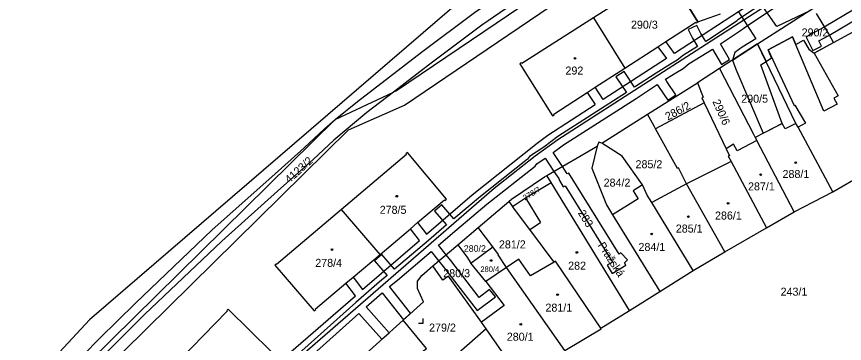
# Model space of a CAD drawing. Extents: x -869103 to -863415, y -1015889 to -1012477.
# Drawn here: x -867399.9 to -867224, y -1013871.7 to -1013802.3 of the extents above; entities that cross this region are included whole.
import ezdxf

# ---------------------------------------------------------------- set-up
doc = ezdxf.new("R2010")
doc.units = 0
for name, color, linetype in [('Hranice parcel', 7, 'Continuous'), ('Parcelní čísla', 7, 'Continuous'), ('Pop  PČ popisy', 7, 'Continuous'), ('Vnitřní kresba', 7, 'Continuous'), ('Věcná břemena k části', 7, 'Continuous'), ('Značky budov', 7, 'Continuous'), ('Značky kultur', 7, 'Continuous')]:
    doc.layers.add(name, color=color, linetype=linetype)

msp = doc.modelspace()

# ---------------------------------------------------------------- linework, layer by layer
at = {"layer": 'Hranice parcel'}
for p, q in [((-867277.34, -1013802.56), (-867270.69, -1013813.22)), ((-867242.47, -1013808.08), (-867250.56, -1013813.33)), ((-867234.33, -1013824.97), (-867242.47, -1013808.08)), ((-867250.56, -1013813.33), (-867255.27, -1013816.38)), ((-867265.84, -1013823.02), (-867255.27, -1013816.38)), ((-867332.19, -1013824.13), (-867319.83, -1013818.34)), ((-867253.84, -1013820.61), (-867264.15, -1013826.09)), ((-867253.84, -1013820.61), (-867249.16, -1013830.36)), ((-867275.59, -1013829.14), (-867265.84, -1013823.02)), ((-867264.43, -1013825.58), (-867265.84, -1013823.02)), ((-867264.15, -1013826.09), (-867264.43, -1013825.58)), ((-867233.85, -1013825.73), (-867234.33, -1013824.97)), ((-867226.53, -1013839.51), (-867233.85, -1013825.73)), ((-867243, -1013827.93), (-867242.65, -1013828.58)), ((-867287.23, -1013836.04), (-867276.54, -1013829.8)), ((-867234.74, -1013843.75), (-867242.65, -1013828.58)), ((-867226.53, -1013839.51), (-867209.64, -1013829.72)), ((-867286.34, -1013837.49), (-867287.23, -1013836.04)), ((-867269.71, -1013864.68), (-867286.34, -1013837.49)), ((-867257.58, -1013837.77), (-867264.97, -1013841.75)), ((-867249.43, -1013852.24), (-867257.58, -1013837.77)), ((-867234.74, -1013843.75), (-867226.53, -1013839.51)), ((-867301.8, -1013847.07), (-867295.3, -1013841.57)), ((-867295.3, -1013841.57), (-867294.72, -1013841.08)), ((-867295.3, -1013841.57), (-867294.53, -1013842.6)), ((-867256.18, -1013856.17), (-867264.97, -1013841.75)), ((-867322.67, -1013852.76), (-867330.82, -1013843.22)), ((-867240.56, -1013847.11), (-867234.74, -1013843.75)), ((-867273.26, -1013844.36), (-867263.25, -1013860.65)), ((-867306.15, -1013850.76), (-867301.8, -1013847.07)), ((-867298.73, -1013851.16), (-867301.8, -1013847.07)), ((-867249.43, -1013852.24), (-867240.56, -1013847.11)), ((-867311.44, -1013855.23), (-867306.15, -1013850.76)), ((-867306.15, -1013850.76), (-867304.22, -1013853.28)), ((-867303.38, -1013854.64), (-867298.73, -1013851.16)), ((-867295.82, -1013855.57), (-867297.61, -1013852.86)), ((-867256.18, -1013856.17), (-867249.43, -1013852.24)), ((-867304.22, -1013853.28), (-867303.38, -1013854.64)), ((-867313.82, -1013857.24), (-867311.44, -1013855.23)), ((-867300.19, -1013858.53), (-867303.38, -1013854.64)), ((-867295.82, -1013855.57), (-867300.19, -1013858.53)), ((-867283.42, -1013873.19), (-867295.82, -1013855.57)), ((-867263.25, -1013860.65), (-867256.18, -1013856.17)), ((-867269.71, -1013864.68), (-867263.25, -1013860.65)), ((-867317.75, -1013866.71), (-867313.44, -1013862.82)), ((-867275.79, -1013868.4), (-867269.71, -1013864.68)), ((-867332.95, -1013880.44), (-867317.75, -1013866.71)), ((-867300.13, -1013868.57), (-867310.38, -1013877.53)), ((-867300.13, -1013868.57), (-867301.12, -1013867.19)), ((-867292.47, -1013879.54), (-867300.13, -1013868.57))]:
    msp.add_line(p, q, dxfattribs=at)
for points in [[(-867198.59, -1013754.65), (-867231.61, -1013768.67), (-867274.19, -1013787.61), (-867319.18, -1013818.03), (-867319.83, -1013818.34)], [(-867244.56, -1013771.73), (-867250.38, -1013776.13), (-867253.52, -1013777.94), (-867257.12, -1013779.67), (-867272.27, -1013786.16), (-867277.68, -1013788.74), (-867282.14, -1013791.26), (-867286.88, -1013794.32), (-867301.07, -1013804.13), (-867312.35, -1013812.6), (-867319.83, -1013818.34)], [(-867250.34, -1013772.25), (-867282.14, -1013785.97), (-867306.94, -1013800.07), (-867384.39, -1013866.64), (-867434.39, -1013920.49), (-867436.42, -1013923.8), (-867438.57, -1013927.32), (-867439.06, -1013927.97), (-867462.7, -1013959.36), (-867480.28, -1013989.66), (-867492.46, -1014014.81)], [(-867332.19, -1013824.13), (-867327.48, -1013820.33), (-867313.84, -1013809.85), (-867302.63, -1013801.4), (-867288.45, -1013791.63), (-867283.44, -1013788.42), (-867279.13, -1013785.97), (-867273.36, -1013783.27), (-867258.47, -1013776.9), (-867254.8, -1013775.21), (-867252.11, -1013773.59)], [(-867434.92, -1013943.41), (-867421.86, -1013928.22), (-867381.87, -1013878.05), (-867329.35, -1013826.35), (-867317.49, -1013821.1), (-867273.34, -1013791.12), (-867238.83, -1013775.51)], [(-867270.69, -1013813.22), (-867263.64, -1013808.67), (-867261.97, -1013807.59), (-867255.62, -1013803.49), (-867255.53, -1013803.63), (-867255.19, -1013803.41), (-867261.88, -1013792.51), (-867262.22, -1013792.73), (-867262.13, -1013792.87), (-867277.34, -1013802.56)], [(-867241.91, -1013794.69), (-867240.22, -1013797.14), (-867240.08, -1013797.65), (-867240.08, -1013798.17), (-867240.33, -1013799), (-867241.24, -1013800.34), (-867284.91, -1013828.43), (-867289.71, -1013831.92), (-867298.4, -1013838.76), (-867342.89, -1013877.33), (-867369, -1013903.98), (-867376.27, -1013912.35), (-867397.67, -1013939.16), (-867399.06, -1013941.39), (-867399.79, -1013942.77), (-867400.13, -1013943.54), (-867401.03, -1013947.17), (-867401.19, -1013951.27), (-867395.05, -1013959.83), (-867379.41, -1013969.96), (-867377.98, -1013971.45), (-867377.11, -1013973.28), (-867377.19, -1013975.36), (-867378.6, -1013978.05)], [(-867242.47, -1013808.08), (-867228.73, -1013799.32), (-867225.18, -1013798.31), (-867222.21, -1013800.13), (-867219.94, -1013804.31)], [(-867277.34, -1013802.56), (-867292.57, -1013812.24), (-867292.64, -1013812.12), (-867292.98, -1013812.34), (-867286.02, -1013823.34), (-867285.68, -1013823.12), (-867285.78, -1013822.97), (-867278.66, -1013818.37), (-867277, -1013817.29), (-867270.69, -1013813.22)], [(-867219.94, -1013804.31), (-867230.46, -1013810.02), (-867225.39, -1013819.12), (-867226.28, -1013819.62), (-867225.61, -1013820.9), (-867228.39, -1013822.35), (-867235.09, -1013806.55)], [(-867235.09, -1013806.55), (-867240.25, -1013809.37), (-867234.69, -1013821.18), (-867234.56, -1013821.11), (-867232.32, -1013824.94), (-867233.85, -1013825.73)], [(-867250.56, -1013813.33), (-867243.38, -1013827.24), (-867243, -1013827.93)], [(-867255.27, -1013816.38), (-867254.06, -1013819.4), (-867254.34, -1013819.56), (-867253.84, -1013820.61)], [(-867319.83, -1013818.34), (-867325.5, -1013822.68), (-867332.5, -1013828.54), (-867336.84, -1013832.6), (-867343.7, -1013838.73), (-867356.28, -1013849.94), (-867372.66, -1013865.5), (-867380.07, -1013872.86), (-867383.55, -1013876.4), (-867387.17, -1013880.32), (-867398.77, -1013893.49)], [(-867447.96, -1013946.46), (-867445.96, -1013941.95), (-867445.44, -1013940.55), (-867444.15, -1013937.25), (-867442.26, -1013934.41), (-867437.14, -1013929.41), (-867431.1, -1013924.19), (-867426.12, -1013919.46), (-867420.37, -1013913.18), (-867414.7, -1013906.89), (-867401.06, -1013891.27), (-867389.4, -1013878.13), (-867385.76, -1013874.22), (-867382.15, -1013870.59), (-867374.7, -1013863.19), (-867358.34, -1013847.58), (-867345.67, -1013836.28), (-867338.79, -1013830.13), (-867334.43, -1013826.12), (-867332.19, -1013824.13)], [(-867398.77, -1013893.49), (-867384.45, -1013875.59), (-867332.19, -1013824.13)], [(-867257.58, -1013837.77), (-867259.24, -1013834.4), (-867259.51, -1013834.53), (-867264.15, -1013826.09)], [(-867234.33, -1013824.97), (-867236.62, -1013826.11), (-867237.26, -1013824.98), (-867243, -1013827.93)], [(-867276.54, -1013829.8), (-867277.65, -1013834.5), (-867274.55, -1013842.26), (-867273.26, -1013844.36)], [(-867275.59, -1013829.14), (-867276.21, -1013828.91), (-867276.54, -1013829.8)], [(-867266.94, -1013838.01), (-867271.21, -1013831.95), (-867275.59, -1013829.14)], [(-867242.65, -1013828.58), (-867246.85, -1013830.77), (-867247.59, -1013829.35), (-867249.16, -1013830.36)], [(-867322.67, -1013852.76), (-867316.21, -1013847.31), (-867314.69, -1013846.03), (-867308.97, -1013841.2), (-867308.87, -1013841.32), (-867308.57, -1013841.06), (-867316.84, -1013831.17), (-867317.15, -1013831.43), (-867317.04, -1013831.55), (-867330.82, -1013843.22)], [(-867249.16, -1013830.36), (-867248.46, -1013831.82), (-867248.7, -1013831.95), (-867248.09, -1013833.08), (-867240.56, -1013847.11)], [(-867294.72, -1013841.08), (-867287.71, -1013836.32), (-867287.23, -1013836.04)], [(-867294.53, -1013842.6), (-867291.79, -1013840.74), (-867286.34, -1013837.49)], [(-867266.94, -1013838.01), (-867268.87, -1013839.28), (-867267.81, -1013841.01), (-867273.26, -1013844.36)], [(-867264.97, -1013841.75), (-867265.92, -1013840.19), (-867266.94, -1013838.01)], [(-867330.82, -1013843.22), (-867344.62, -1013854.89), (-867344.71, -1013854.77), (-867345.02, -1013855.03), (-867336.68, -1013864.79), (-867336.27, -1013864.45), (-867336.38, -1013864.33), (-867329.91, -1013858.87), (-867328.39, -1013857.58), (-867322.67, -1013852.76)], [(-867285.67, -1013854.4), (-867290.88, -1013847.46), (-867294.53, -1013842.6)], [(-867297.61, -1013852.86), (-867297.53, -1013852.79), (-867298.73, -1013851.16)], [(-867285.67, -1013854.4), (-867290.74, -1013857.29), (-867293.22, -1013853.8), (-867295.82, -1013855.57)], [(-867275.79, -1013868.4), (-867285.39, -1013854.24), (-867285.67, -1013854.4)], [(-867301.12, -1013867.19), (-867308.13, -1013857.38), (-867309.3, -1013858.22), (-867311.44, -1013855.23)], [(-867313.44, -1013862.82), (-867314.73, -1013860), (-867314.69, -1013858.49), (-867313.82, -1013857.24)], [(-867300.19, -1013858.53), (-867296.31, -1013863.6), (-867301.12, -1013867.19)], [(-867346.08, -1013873.66), (-867345.73, -1013873.43), (-867354.94, -1013864.4), (-867355.22, -1013864.69), (-867355.1, -1013864.8), (-867367.68, -1013877.69), (-867380.27, -1013890.57), (-867380.37, -1013890.47), (-867380.66, -1013890.76), (-867371.49, -1013899.69), (-867371.22, -1013899.41), (-867371.32, -1013899.31), (-867365.41, -1013893.25), (-867363.99, -1013891.79), (-867358.76, -1013886.41), (-867352.86, -1013880.38), (-867351.44, -1013878.92), (-867346.19, -1013873.54), (-867346.08, -1013873.66)], [(-867313.62, -1013873.39), (-867312.83, -1013872.77), (-867317.75, -1013866.71)], [(-867283.42, -1013873.19), (-867275.67, -1013868.55), (-867275.79, -1013868.4)]]:
    msp.add_lwpolyline(points, dxfattribs=at)
at = {"layer": 'Vnitřní kresba'}
for p, q in [((-867240.22, -1013797.14), (-867260.14, -1013810.1)), ((-867263.64, -1013808.67), (-867261.82, -1013811.19)), ((-867260.14, -1013810.1), (-867261.97, -1013807.59)), ((-867261.82, -1013811.19), (-867275.27, -1013819.88)), ((-867275.27, -1013819.88), (-867277, -1013817.29)), ((-867278.66, -1013818.37), (-867276.95, -1013820.97)), ((-867287.02, -1013827.48), (-867276.95, -1013820.97)), ((-867289.32, -1013829.14), (-867287.02, -1013827.48)), ((-867303.12, -1013840.13), (-867289.32, -1013829.14)), ((-867248.09, -1013833.08), (-867257.58, -1013837.77)), ((-867312.79, -1013848.5), (-867303.12, -1013840.13)), ((-867291.79, -1013840.74), (-867288.61, -1013845.99)), ((-867314.3, -1013849.81), (-867316.21, -1013847.31)), ((-867314.69, -1013846.03), (-867312.79, -1013848.5)), ((-867290.88, -1013847.46), (-867288.61, -1013845.99)), ((-867326.36, -1013860.24), (-867314.3, -1013849.81)), ((-867328.39, -1013857.58), (-867326.36, -1013860.24)), ((-867327.87, -1013861.55), (-867329.91, -1013858.87)), ((-867342.68, -1013874.37), (-867327.87, -1013861.55))]:
    msp.add_line(p, q, dxfattribs=at)
at = {"layer": 'Věcná břemena k části'}
for points in [[(-867240.22, -1013798.64), (-867246.67, -1013803), (-867246.98, -1013803.28), (-867252.32, -1013806.83), (-867253.48, -1013807.54), (-867254.53, -1013805.84), (-867255.37, -1013804.15), (-867257.21, -1013805.05), (-867256.33, -1013806.84), (-867255.23, -1013808.61), (-867258.24, -1013810.48), (-867259.55, -1013811.51), (-867260.96, -1013812.4), (-867264.02, -1013814.26), (-867268.61, -1013817.3), (-867270.84, -1013813.92), (-867272.56, -1013815.04), (-867270.33, -1013818.42), (-867284.91, -1013827.73), (-867287.91, -1013830.01), (-867290.92, -1013831.99), (-867291.31, -1013832.55), (-867301.33, -1013840.45), (-867306.97, -1013845.19), (-867309.52, -1013842.22), (-867311.08, -1013843.56), (-867308.54, -1013846.51), (-867312.4, -1013849.8), (-867319.59, -1013855.93), (-867322.3, -1013852.76), (-867323.84, -1013854.12), (-867321.16, -1013857.25), (-867322.77, -1013858.6), (-867327.82, -1013862.98), (-867341.99, -1013875.67)], [(-867257.45, -1013799.74), (-867255.19, -1013803.41), (-867250.37, -1013801.71)], [(-867340.93, -1013877.62), (-867327.17, -1013865.29), (-867322.27, -1013870.79), (-867320.75, -1013869.42), (-867325.63, -1013863.93), (-867322.18, -1013860.94), (-867317.69, -1013866.66), (-867316.17, -1013865.28), (-867320.62, -1013859.61), (-867318.97, -1013858.25), (-867311.83, -1013852.15), (-867310.19, -1013854.18), (-867309.28, -1013855.31), (-867302.07, -1013864.7), (-867298.13, -1013861.81), (-867299.41, -1013860.21), (-867301.64, -1013861.89), (-867307.66, -1013854.05), (-867308.63, -1013852.85), (-867310.27, -1013850.82), (-867306.35, -1013847.49), (-867299.97, -1013842.13), (-867289.71, -1013834.05), (-867289.38, -1013833.57), (-867287.56, -1013832.37), (-867285.72, -1013835.16), (-867284.72, -1013836.69), (-867284.58, -1013837.07), (-867283.78, -1013838.41), (-867283.35, -1013838.21), (-867273.32, -1013854.4), (-867274.43, -1013855.08), (-867273.35, -1013856.82), (-867270.46, -1013855.05), (-867270.76, -1013854.56), (-867270.1, -1013853.91), (-867271.54, -1013852.45), (-867271.85, -1013852.75), (-867282.55, -1013835.51), (-867282.89, -1013835.67), (-867283.92, -1013834.11), (-867285.86, -1013831.16), (-867283.67, -1013829.51), (-867268.28, -1013819.68), (-867263.78, -1013816.69), (-867263.52, -1013817.15), (-867261.53, -1013820.02), (-867259.85, -1013818.86), (-867261.78, -1013816.07), (-867262.04, -1013815.59), (-867259.82, -1013814.24), (-867258.31, -1013813.27), (-867257, -1013812.26), (-867253.22, -1013809.91), (-867252.07, -1013809.2), (-867250.17, -1013812.43), (-867248.41, -1013811.39), (-867250.34, -1013808.1), (-867245.66, -1013804.98), (-867245.35, -1013804.7), (-867238.69, -1013800.22)], [(-867246.52, -1013801.24), (-867245.4, -1013803.02), (-867242.88, -1013807.01), (-867245.78, -1013808.78), (-867247.32, -1013809.89), (-867247.8, -1013811.54), (-867242.47, -1013808.08), (-867240.67, -1013811.81), (-867239.49, -1013811.07), (-867240.25, -1013809.37), (-867235.09, -1013806.55), (-867234.38, -1013808.22), (-867232.74, -1013807.26), (-867231.63, -1013809.17), (-867230.46, -1013810.02), (-867226.38, -1013807.81), (-867226.87, -1013806.88), (-867227.36, -1013805.95), (-867229.96, -1013801.66)], [(-867231.41, -1013801.03), (-867238.36, -1013804.42), (-867241.24, -1013800.34)], [(-867221.9, -1013800.69), (-867228.35, -1013804.53), (-867231.26, -1013806.05), (-867232.17, -1013806.68), (-867230.77, -1013809.5), (-867228.93, -1013808.58), (-867229.5, -1013807.44), (-867227.33, -1013806.31), (-867220.92, -1013802.51), (-867220.33, -1013802.16), (-867219.83, -1013802.95), (-867210.39, -1013817.93), (-867209.7, -1013818.79), (-867208, -1013817.55), (-867208.83, -1013816.45), (-867218.82, -1013800.59)]]:
    msp.add_lwpolyline(points, dxfattribs=at)
msp.add_lwpolyline([(-867247.13, -1013813.45), (-867241.27, -1013827.04), (-867237.26, -1013824.98), (-867241.78, -1013812.5), (-867240.67, -1013811.81), (-867242.47, -1013808.08), (-867247.8, -1013811.54)], close=True, dxfattribs=at)
at = {"layer": 'Značky budov'}
for centre in [(-867281.24, -1013811.15), (-867234.39, -1013833.29), (-867241.83, -1013835.83), (-867319.1, -1013840.42), (-867248.74, -1013841.92), (-867257.18, -1013844.75), (-867264.96, -1013848.43), (-867332.86, -1013851.75), (-867280.85, -1013852.36), (-867299.07, -1013854.07), (-867284.96, -1013861.34), (-867292.77, -1013867.61)]:
    msp.add_circle(centre, 0.175, dxfattribs=at)
at = {"layer": 'Značky kultur'}
for p, q in [((-867313.52, -1013867.39), (-867313.52, -1013866.39)), ((-867314.52, -1013867.39), (-867313.52, -1013867.39))]:
    msp.add_line(p, q, dxfattribs=at)

# ---------------------------------------------------------------- texts
at = {"layer": 'Parcelní čísla'}
for s, height, p in [('290/3', 1.7, (-867269.37, -1013804.85)), ('290/2', 1.7, (-867233.12, -1013806.49)), ('292', 1.7, (-867283.28, -1013814.59)), ('290/5', 1.7, (-867245.95, -1013820.57)), ('285/2', 1.7, (-867268.4, -1013834.48)), ('288/1', 1.7, (-867237.18, -1013836.56)), ('284/2', 1.7, (-867275.18, -1013838.38)), ('287/1', 1.7, (-867244.51, -1013839.18)), ('278/5', 1.7, (-867322.74, -1013844.16)), ('286/1', 1.7, (-867251.52, -1013845.37)), ('285/1', 1.7, (-867259.85, -1013848.14)), ('280/2', 1.4, (-867304.87, -1013852.22)), ('281/2', 1.7, (-867297.41, -1013851.5)), ('284/1', 1.7, (-867267.77, -1013852.04)), ('278/4', 1.7, (-867336.42, -1013855.42)), ('282', 1.7, (-867282.72, -1013856.02)), ('280/3', 1.7, (-867309.23, -1013857.62)), ('280/4', 1.19, (-867301.35, -1013856.52)), ('243/1', 1.7, (-867237.59, -1013861.54)), ('281/1', 1.7, (-867287.53, -1013864.92)), ('279/2', 1.7, (-867312.24, -1013869.16)), ('280/1', 1.7, (-867295.74, -1013871.1))]:
    msp.add_text(s, height=height, dxfattribs=at).set_placement(p)
for s, height, rotation, p in [('286/2', 1.7, 28, (-867261.56, -1013824.39)), ('290/6', 1.7, 294, (-867252.11, -1013820.32)), ('4123/2', 1.7, 42, (-867341.96, -1013837.79)), ('278/7', 1.19, 31, (-867291.86, -1013841.38)), ('283', 1.7, 302, (-867280.71, -1013843.98))]:
    msp.add_text(s, height=height, rotation=rotation, dxfattribs=at).set_placement(p)
at = {"layer": 'Pop  PČ popisy'}
msp.add_text('Pražská', height=1.7, rotation=303, dxfattribs=at).set_placement((-867276.48, -1013850.84))

doc.saveas('drawing.dxf')
